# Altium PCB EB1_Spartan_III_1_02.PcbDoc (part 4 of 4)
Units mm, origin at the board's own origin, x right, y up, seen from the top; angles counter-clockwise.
Board outline 165.1 x 115.01 mm, 6 copper layers (Top Layer, MidLayer1, VCC Plane, GND Plane, MidLayer2, Bottom Layer); 356 components, 386 nets, 1788 pads, 779 vias.
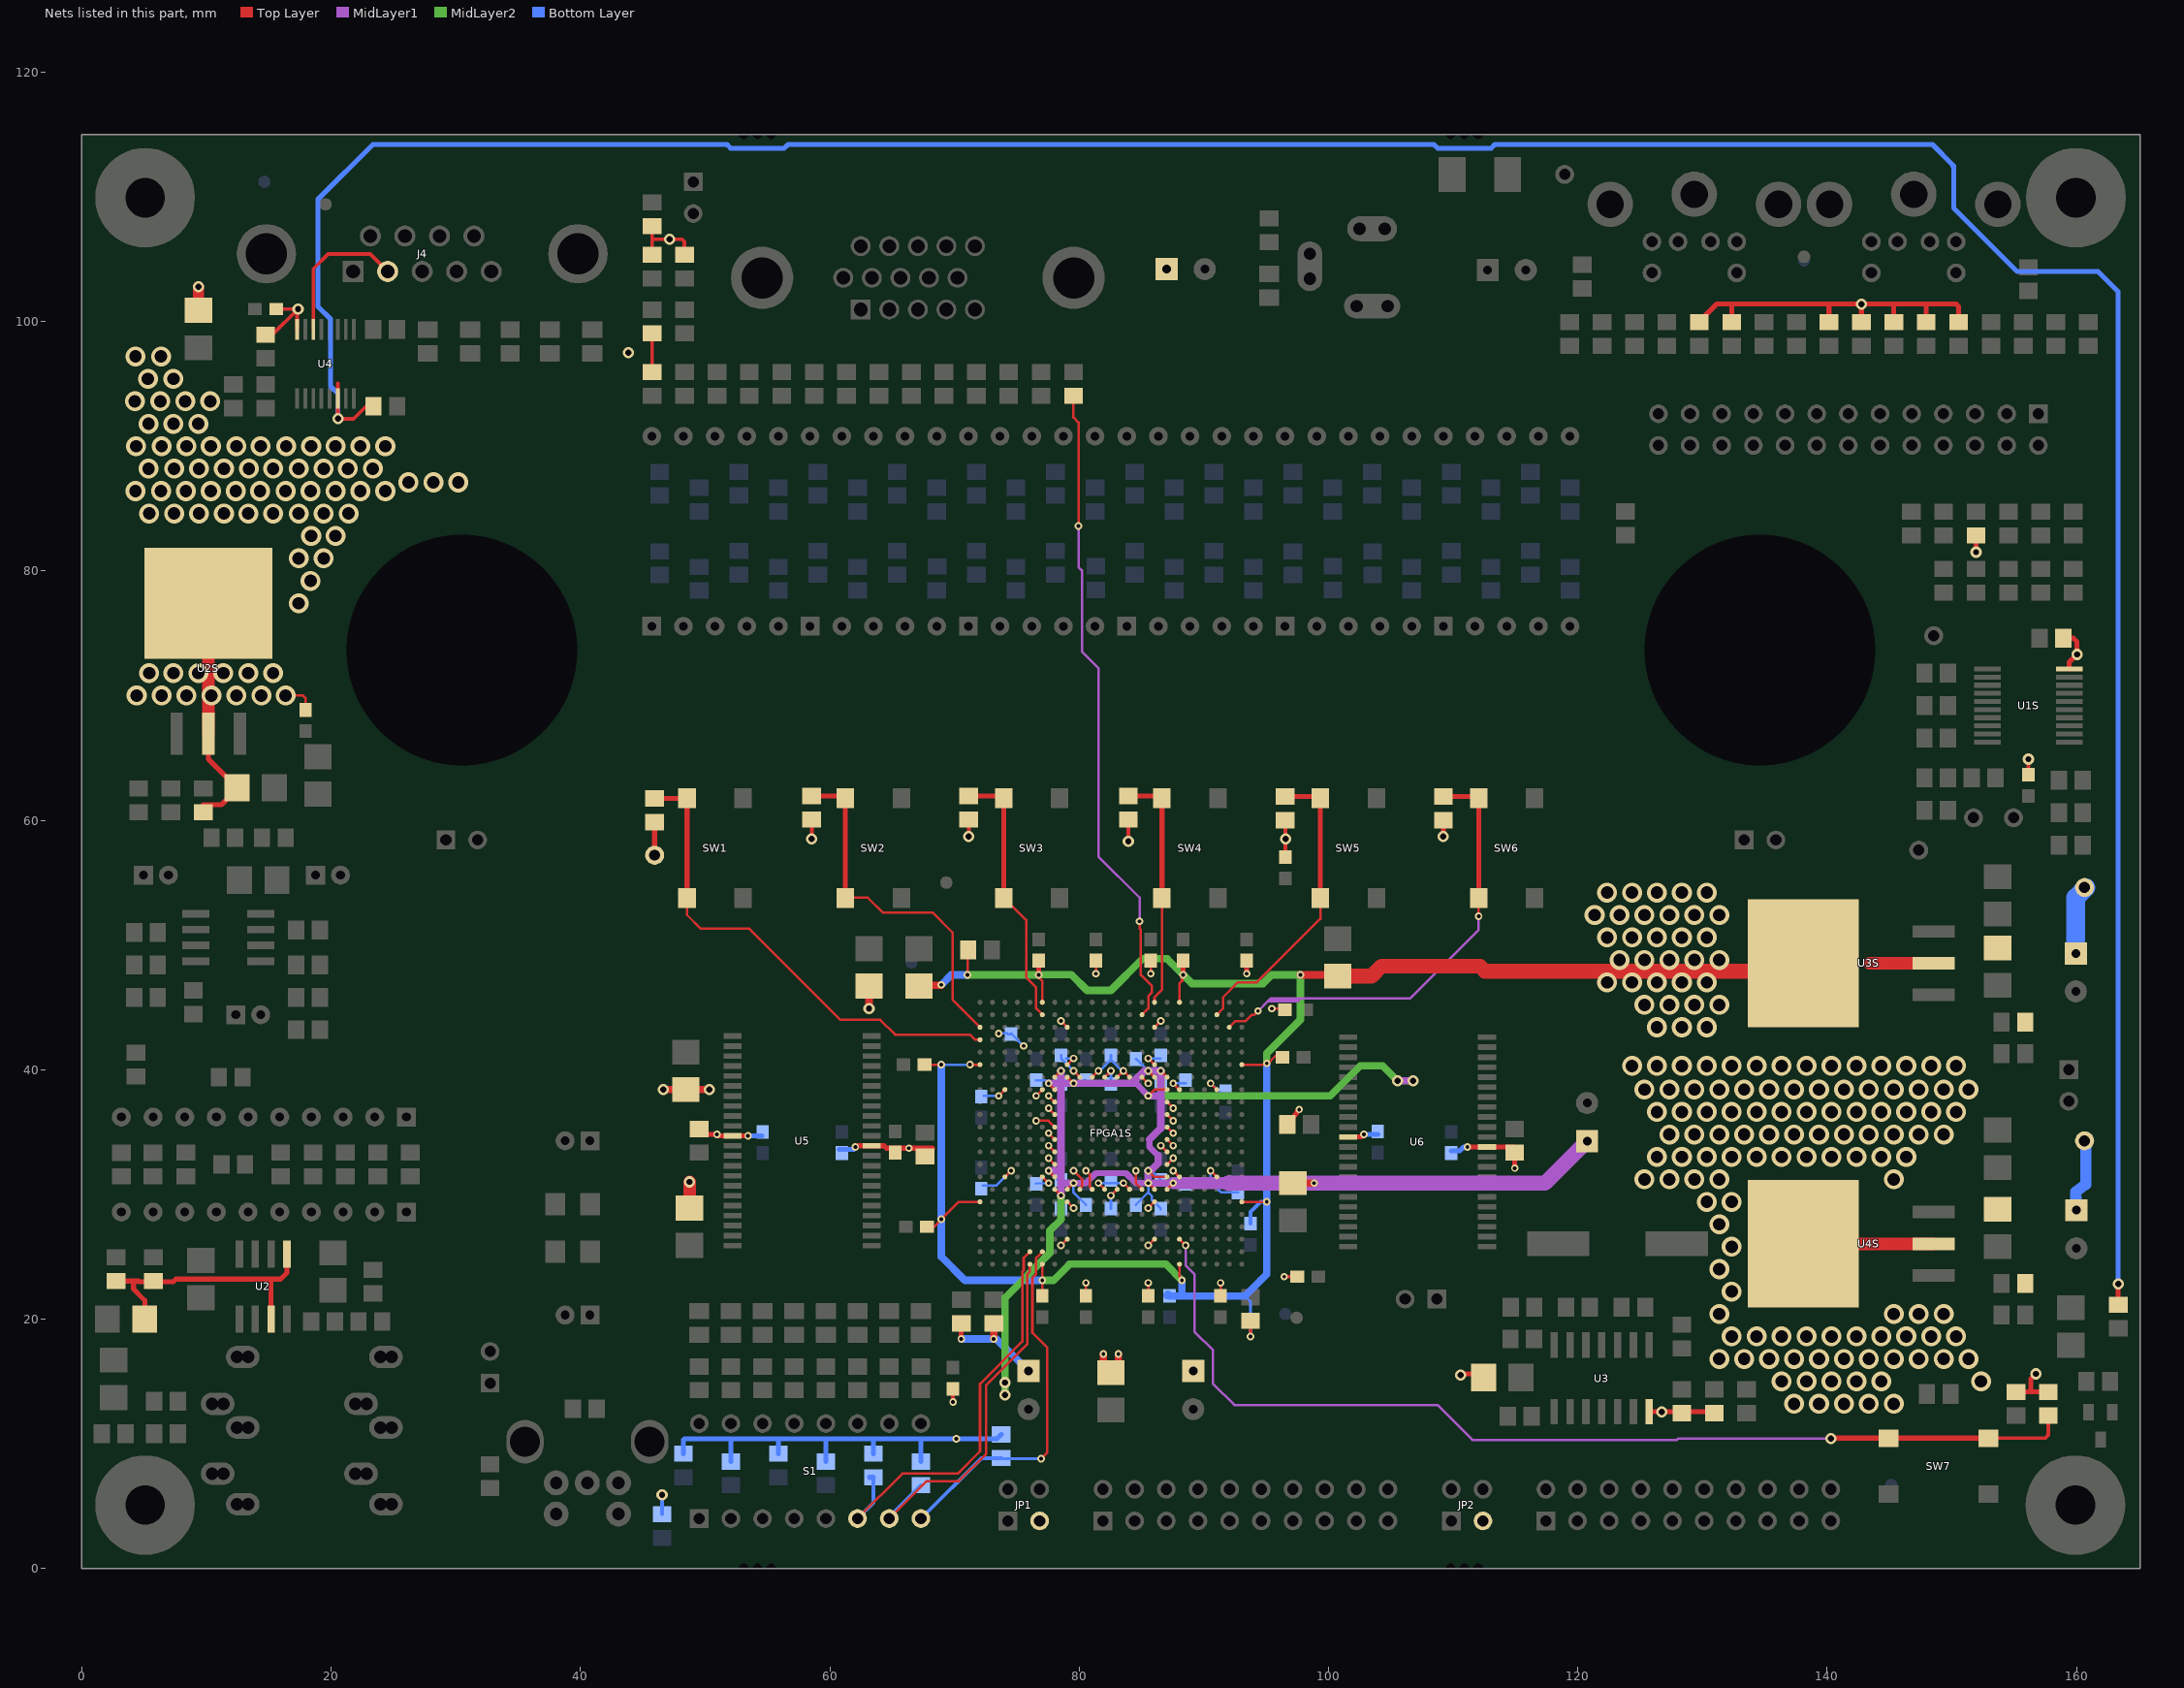
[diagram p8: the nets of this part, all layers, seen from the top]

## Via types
v1: diameter 0.6, hole 0.3, Top Layer to Bottom Layer, tented both sides, 427 vias
v2: diameter 1.6, hole 1, Top Layer to Bottom Layer, 224 vias
v3: diameter 0.9, hole 0.5, Top Layer to Bottom Layer, tented both sides, 126 vias
v4: diameter 1.27, hole 0.711, Top Layer to Bottom Layer, tented both sides, 2 vias

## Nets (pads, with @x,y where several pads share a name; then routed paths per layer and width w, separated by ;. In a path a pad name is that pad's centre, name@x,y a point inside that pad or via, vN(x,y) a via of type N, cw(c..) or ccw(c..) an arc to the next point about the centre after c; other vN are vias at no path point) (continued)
SW_DIP5: FPGA1S.AA5 R16.1 S1.6 | length 33.9
  Top Layer w0.2: S1.6@62.23,4 65.83,7.6 70.25,7.6 72.05,9.4 72.05,14.8 75.45,18.2 75.45,23.8 75.55,23.9 75.55,24.9 FPGA1S.AA5@76.05,25.4
  Bottom Layer w0.3: S1.6@62.23,4 63.5,5.27 R16.1@63.5,7.305
  Bottom Layer w0.4: R16.1@63.185,7.305 R16.1@63.5,7.305
SW_DIP6: FPGA1S.AB5 R17.1 S1.7 | length 30.3
  Top Layer w0.2: S1.7@64.77,4 67.77,7 70.35,7 72.55,9.2 72.55,14.7 75.85,18 75.85,23.6 76.05,23.8 FPGA1S.AB5@76.05,24.4
  Bottom Layer w0.3: S1.7@64.77,4 64.77,4.13 R17.1@67.31,6.67
SW_DIP7: FPGA1S.AA6 R18.1 S1.8 | length 29.2
  Top Layer w0.2: v1(76.95,8.8) 77.45,9.3 77.45,17.7 76.25,18.9 76.25,23.3 76.55,23.6 76.55,24.9 FPGA1S.AA6@77.05,25.4
  Bottom Layer w0.2: R18.1@73.95,8.8 v1(76.95,8.8)
  Bottom Layer w0.3: S1.8@67.31,4 72.16,8.85 R18.1@73.75,8.85
  Bottom Layer w0.4: S1.8@67.09,4.07 S1.8@67.165,4.145
SW_TEST: FPGA1S.Y17 R21.2 SW7.1 SW7.2 | length 83.3
  Top Layer w0.2: FPGA1S.Y17@88.05,26.4 v1(88.55,25.9)
  Top Layer w0.3: SW7.2@153.09,10.45 157.5,10.45 157.75,10.7 R21.2@157.75,12.25
  Top Layer w0.4: v3(140.29,10.4) 140.34,10.45 SW7.1@144.94,10.45 SW7.2@152.95,10.45 SW7.2@153.09,10.45
  MidLayer1 w0.2: v1(88.55,25.9) 88.55,24.3 89.25,23.6 89.25,19 90.75,17.5 90.75,14.8 92.45,13.1 108.75,13.1 111.55,10.3 127.95,10.3 128.05,10.4 v3(140.29,10.4)
SW_USER0: FPGA1S.D1 R9.2 SW1.1 SW1.2 | length 39.6
  Top Layer w0.2: SW1.1@48.55,53.775 48.55,52.4 49.65,51.3 53.55,51.3 60.85,44 64.05,44 65.25,42.8 71.25,42.8 71.65,42.4 FPGA1S.D1@72.05,42.4
  Top Layer w0.4: R9.2@45.95,61.75 48.515,61.75 SW1.2@48.55,61.785 SW1.1@48.55,53.775
SW_USER1: FPGA1S.C1 R10.2 SW2.1 SW2.2 | length 29
  Top Layer w0.2: SW2.1@61.25,53.8 63.05,53.8 64.25,52.6 68.25,52.6 69.85,51 69.85,45.6 FPGA1S.C1@72.05,43.4
  Top Layer w0.4: R10.2@58.55,61.95 61.085,61.95 SW2.2@61.25,61.785 61.25,53.8 SW2.1@61.25,53.775
SW_USER2: FPGA1S.B6 R19.2 SW3.1 SW3.2 | length 21.5
  Top Layer w0.2: SW3.1@73.95,53.775 73.975,53.775 75.75,52 75.75,47.4 76.55,46.6 76.55,44.9 FPGA1S.B6@77.05,44.4
  Top Layer w0.4: R19.2@71.15,61.95 73.9,61.95 SW3.2@73.95,62 ; SW3.1@73.95,53.775 SW3.2@73.95,61.785
SW_USER3: FPGA1S.A15 R20.2 SW4.1 SW4.2 | length 19.3
  Top Layer w0.2: FPGA1S.A15@86.05,45.4 86.05,45.8 86.65,46.4 SW4.1@86.65,53.775
  Top Layer w0.4: R20.2@83.95,61.95 86.5,61.95 SW4.2@86.55,62 ; SW4.1@86.65,53.775 SW4.2@86.65,61.785
SW_USER4: FPGA1S.B20 R22.2 SW5.1 SW5.2 | length 24.6
  Top Layer w0.2: FPGA1S.B20@91.05,44.4 91.55,44.9 91.55,45.8 92.75,47 94.25,47 99.35,52.1 SW5.1@99.35,53.775
  Top Layer w0.4: R22.2@96.52,61.91 99.225,61.91 SW5.2@99.35,61.785 SW5.1@99.35,53.775
SW_USER5: FPGA1S.C21 R23.2 SW6.1 SW6.2 | length 39.4
  Top Layer w0.2: FPGA1S.C21@92.05,43.4 92.55,43.9 93.35,43.9 93.85,44.4 94.05,44.4 v1(94.35,44.7) ; v1(112.05,52.3) SW6.1@112.05,53.775
  Top Layer w0.4: R23.2@109.22,61.91 111.925,61.91 SW6.2@112.05,61.785 SW6.1@112.05,53.775
  MidLayer1 w0.2: v1(94.35,44.7) 95.15,45.5 ; v1(112.05,52.3) 112.05,51.2 106.55,45.7 97.75,45.7 ; 95.15,45.5 97.55,45.5 97.75,45.7 ; 95.15,45.5 95.35,45.7 97.75,45.7
TX: J4.2 U4.14 | length 11.9
  Top Layer w0.3: U4.14@18.575,99.375 18.575,104.225 19.75,105.4 23.15,105.4 J4.2@24.535,104.015
V-232: C23.1 R30S.2 U4.6 | length 259.5
  Top Layer w0.3: 20.525,95.025 U4.6@20.525,93.825 20.525,92.425 v3(20.55,92.2) 21.8,92.2 23.1,93.5 C23.1@23.4,93.8
  Top Layer w0.4: R30S.2@163.35,21.15 v3(163.35,22.8)
  Bottom Layer w0.4: v3(20.55,92.2) 20.55,94.2 19.95,94.8 19.95,100.2 18.95,101.2 18.95,109.8 23.35,114.2 51.75,114.2 52.05,113.9 56.35,113.9 56.65,114.2 108.45,114.2 108.75,113.9 113.05,113.9 113.35,114.2 148.45,114.2 150.15,112.5 150.15,112.4 ; 150.1,112.45 150.15,112.4 ; v3(163.35,22.8) 163.35,102.4 161.75,104 155.25,104 150.15,109.1 150.15,112.4
VAREF: C4.1 R7.2 R8.1 U2.3 U2.5 | length 22.4
  Top Layer w0.4: R8.1@2.75,23.05 4.15,23.05 ; 4.55,23 5.75,23 7.35,23 7.55,23.2 15.15,23.2 ; 4.55,23.05 4.15,23.05 ; C4.1@5.05,20 5.05,21.5 4.15,22.4 4.15,23.05 ; U2.3@15.185,20 15.185,23.165 15.15,23.2 ; U2.5@16.455,25.2 16.455,23.705 16.195,23.445 15.95,23.2 15.15,23.2
  Top Layer w0.6: R7.2@5.75,23.05 5.8,23.05 R7.2@5.95,23.2
VCC: C1S.1 C2S.1 C3S.1 C4S.1 C5S.1 C6S.1 C7S.1 C8S.1 C13S.1 C14S.1 C15S.1 C16S.1 C17S.1 C18.1 C18S.1 C19.1 C19S.1 C20S.1 C21.1 C21S.1 C22S.1 C23S.1 C24.1 C24S.1 C25.2 C25S.1 C26.2 C26S.1 C27.2 C27S.1 C28.2 C28S.1 C29.2 C29S.1 C30S.1 C31S.1 C32S.1 C33S.1 C34S.1 C51S.1 C54S.1 C55S.1 C56S.1 C57S.1 C68S.1 C69S.1 C74S.1 C80S.1 FPGA1S.C8 FPGA1S.C15 FPGA1S.F8 FPGA1S.F15 FPGA1S.G9 FPGA1S.G10 FPGA1S.G11 FPGA1S.G12 FPGA1S.G13 FPGA1S.G14 FPGA1S.H3 FPGA1S.H6 FPGA1S.H17 FPGA1S.H20 FPGA1S.J7 FPGA1S.J16 FPGA1S.K7 FPGA1S.K16 FPGA1S.L7 FPGA1S.L16 FPGA1S.M7 FPGA1S.M16 FPGA1S.N7 FPGA1S.N16 FPGA1S.P7 FPGA1S.P16 FPGA1S.R3 FPGA1S.R6 FPGA1S.R17 FPGA1S.R20 FPGA1S.T9 FPGA1S.T10 FPGA1S.T11 FPGA1S.T12 FPGA1S.T13 FPGA1S.T14 FPGA1S.U8 FPGA1S.U15 FPGA1S.Y8 FPGA1S.Y15 JP1.3 JP2.3 R9.1 R10.1 R11.2 R12.2 R13.2 R13S.1 R14.2 R14S.1 R15.2 R15S.1 R16.2 R16S.1 R17.2 R17S.1 R18.2 R18S.1 R19.1 R19S.1 R20.1 R20S.1 R21.1 R22.1 R23.1 R32S.2 R73.2 R82.1 R96.2 R97.2 R98.2 R99.2 TP7S.1 U1S.20 U2S.2 U2S.4 U3.14 U4.16 U5.11 U5.33 U6.11 U6.33 | length 231.3
  Top Layer w0.2: v2(16.35,70) 17.75,70 17.95,69.8 C3S.1@17.95,68.85 ; v1(73.55,37.9) FPGA1S.H3@74.05,38.4 ; FPGA1S.R3@74.05,31.4 v1(74.55,31.9) ; v1(76.55,35.9) 77.55,35.9 FPGA1S.L7@78.05,35.4 ; v1(76.55,37.9) FPGA1S.H6@77.05,38.4 ; FPGA1S.R6@77.05,31.4 v1(77.55,30.9) ; v1(77.55,32.9) FPGA1S.P7@78.05,32.4 ; v1(77.55,33.9) FPGA1S.N7@78.05,33.4 ; v1(77.55,34.9) FPGA1S.M7@78.05,34.4 ; v1(77.55,36.9) FPGA1S.K7@78.05,36.4 ; v1(77.55,37.9) FPGA1S.J7@78.05,37.4 ; v1(78.55,25.9) FPGA1S.Y8@79.05,26.4 ; v1(78.55,43.9) FPGA1S.C8@79.05,43.4 ; FPGA1S.U8@79.05,29.4 v1(79.55,28.9) ; FPGA1S.F8@79.05,40.4 v1(79.55,40.9) ; v1(79.55,31.9) 80.25,31.2 80.25,30.7 FPGA1S.T9@80.05,30.4 ; v1(79.55,39.9) FPGA1S.G9@80.05,39.4 ; C7S.1@80.55,21.85 v1(80.55,22.9) ; v1(80.55,31.9) 80.85,31.6 80.85,30.6 FPGA1S.T10@81.05,30.4 ; FPGA1S.G10@81.05,39.4 v1(81.55,39.9) ; v1(81.35,47.7) C16S.1@81.35,48.7 ; v1(81.55,30.9) FPGA1S.T11@82.05,30.4 ; FPGA1S.G11@82.05,39.4 v1(82.55,39.9) ; v1(82.55,29.9) FPGA1S.T12@83.05,30.4 ; FPGA1S.G12@83.05,39.4 v1(83.55,39.9) 83.95,39.5 FPGA1S.G13@84.05,39.4 ; v1(83.55,30.9) FPGA1S.T13@84.05,30.4 ; v1(84.55,31.9) 84.55,30.9 FPGA1S.T14@85.05,30.4 ; FPGA1S.G14@85.05,39.4 v1(85.55,38.9) ; C29S.1@85.55,21.85 v1(85.55,22.9) v1@85.55,23 ; v1(85.55,25.9) FPGA1S.Y15@86.05,26.4 ; v1(85.55,28.9) FPGA1S.U15@86.05,29.4 ; v1(85.55,40.9) FPGA1S.F15@86.05,40.4 ; v1(85.75,47.7) C24S.1@85.75,48.75 ; FPGA1S.C15@86.05,43.4 v1(86.55,43.9) ; v1(86.55,33.9) FPGA1S.N16@87.05,33.4 ; FPGA1S.P16@87.05,32.4 v1(87.55,32.9) ; FPGA1S.M16@87.05,34.4 v1(87.55,33.9) ; FPGA1S.L16@87.05,35.4 v1(87.55,34.9) ; FPGA1S.K16@87.05,36.4 v1(87.55,35.9) ; FPGA1S.J16@87.05,37.4 v1(87.55,36.9) ; v1(87.55,31.9) FPGA1S.R17@88.05,31.4 ; v1(87.55,38.9) FPGA1S.H17@88.05,38.4 ; v1(90.55,31.9) FPGA1S.R20@91.05,31.4 ; v1(90.55,38.9) FPGA1S.H20@91.05,38.4 ; C2S.1@91.35,21.85 91.35,22.8 v1(91.35,22.9) ; v1(95.45,44.9) 96.5,44.9 96.55,44.9 96.532,44.795 C1S.1@96.5,44.6
  Top Layer w0.3: C21.1@14.75,98.95 15.3,98.95 v3@17.275,100.925 ; C26S.1@15.6,101 v3(17.35,101) v3@17.275,100.925 ; U4.16@17.275,99.375 v3@17.275,100.925 ; C24.1@45.75,95.95 R96.2@45.75,99.05 ; R97.2@45.75,105.35 45.75,106.6 ; R99.2@45.75,107.65 45.75,106.6 ; R98.2@48.35,105.35 48.35,106.4 48.15,106.6 v3(47.15,106.6) 45.75,106.6 ; v3(58.55,58.5) R10.1@58.55,60.05 R10.1@58.55,60.1 ; v1(69.885,13.345) C13S.1@69.885,14.395 C13S.1@69.885,14.445 ; v3(71.15,58.7) R19.1@71.15,60.05 ; v3(83.95,58.3) R20.1@83.95,60 ; v1(96.45,23.4) C8S.1@97.5,23.4 C8S.1@97.55,23.4 ; R22.1@96.52,60.01 96.55,59.98 v3(96.55,58.5) C25S.1@96.55,57.05 C25S.1@96.55,57 ; C21S.1@156.15,63.65 v3(156.15,64.9)
  Top Layer w0.4: R32S.2@9.75,61.25 11.2,61.25 12.45,62.5 C74S.1@12.45,62.6 10.15,64.9 U2S.2@10.15,66.95 ; TP7S.1@45.95,57.2 R9.1@45.95,59.85 ; C26.2@49.55,34.8 v1(50.95,34.8) 51.06,34.69 U5.11@52.21,34.69 v1(53.44,34.69) ; v1(62.05,33.8) 62.25,33.9 63.36,33.9 U5.33@63.45,33.9 ; U5.33@63.36,33.89 64.36,33.89 64.55,33.7 65.25,33.7 v1(66.35,33.7) 67.65,33.7 68.25,33.7 ; v1(93.45,47.7) C4S.1@93.45,48.75 ; C27.2@97.05,36 v1(97.65,36.8) ; U6.11@101.575,34.6 102.65,34.6 v1(102.85,34.8) ; v3(109.2,58.7) 109.22,58.72 R23.1@109.22,60.01 ; v3(110.6,15.5) 110.7,15.6 C56S.1@112.45,15.6 ; v1(111.15,33.8) U6.33@112.725,33.8 ; U6.33@112.75,33.8 U6.33@112.725,33.8 ; v1(114.95,32.1) C25.2@114.95,33.3 ; C25.2@114.95,33.8 114.935,33.8 U6.33@112.725,33.8 ; U3.14@125.73,12.565 v3(126.75,12.565) 128.35,12.565 130.435,12.565 R82.1@130.55,12.45 ; R19S.1@129.75,99.95 129.75,100 131.15,101.4 132.35,101.4 ; R18S.1@132.35,100.1 132.35,101.4 ; R17S.1@140.15,99.95 140.15,101.4 ; R16S.1@142.75,99.95 v3(142.75,101.4) ; R15S.1@145.35,99.95 145.35,101.4 ; R20S.1@147.95,99.95 147.95,101.4 ; R14S.1@150.55,99.95 150.55,101.2 150.35,101.4 147.95,101.4 ; v3(151.95,81.5) R13S.1@151.95,82.85 ; R73.2@155.15,14.15 156.35,14.15 ; v3(156.75,15.6) 156.35,15.2 156.35,14.15 ; R21.1@157.75,14.15 156.35,14.15 ; C68S.1@158.85,74.6 C68S.1@158.95,74.6 159.75,74.6 160.05,74.3 v3(160.05,73.3) 159.425,72.675 U1S.20@159.425,72.125 ; 132.35,101.4 140.15,101.4 ; 140.15,101.4 v3(142.75,101.4) ; v3(142.75,101.4) 145.35,101.4 ; 145.35,101.4 147.95,101.4
  Top Layer w0.6: v3(46.65,38.4) C55S.1@48.45,38.4 v3(50.35,38.4) ; v3(63.15,44.9) C54S.1@63.15,46.7 ; C57S.1@81.95,15.7 v1(81.95,17.2) ; C57S.1@83.15,16.2 v1(83.15,17.2)
  Top Layer w0.9: C18.1@9.35,100.8 C18.1@9.35,100.9 v3(9.35,102.8)
  Top Layer w1: U2S.4@10.05,74.6 10.15,74.5 10.15,71.8 10.15,70 U2S.2@10.15,66.95 ; C19.1@48.75,28.9 v3(48.75,31)
  Bottom Layer w0.2: C15S.1@72.25,30.7 73.35,30.7 v1(74.55,31.9) ; C27S.1@72.35,37.9 v1(73.55,37.9) ; v1(73.55,42.9) 74.25,42.9 74.3,42.85 C34S.1@74.55,42.85 ; C34S.1@74.55,42.9 74.575,42.875 v1(75.55,41.9) ; C5S.1@76.55,30.85 v1(77.55,30.9) ; C32S.1@78.55,41.15 78.55,40.9 v1(79.55,39.9) ; C32S.1@78.95,40.9 v1(79.55,40.9) ; v1(81.55,30.9) 82.55,30.9 v1(83.55,30.9) ; v1(81.55,39.9) 81.65,39.9 C28S.1@82.55,40.8 ; C80S.1@82.55,28.85 v1(82.55,29.9) ; C23S.1@82.55,38.85 v1(82.55,39.9) ; C28S.1@82.55,41.15 C28S.1@82.55,40.8 ; v1@83.55,40 v1(83.55,39.9) 83.45,39.9 C28S.1@82.55,40.8 ; v1(85.55,40.9) C19S.1@86.55,40.9 ; v1(87.55,38.9) C31S.1@88.55,38.9 ; v1(90.55,31.9) 90.55,31 91.4,30.15 C14S.1@92.75,30.15 ; v1(90.55,38.9) 91.531,38.009 C33S.1@91.65,37.9
  Bottom Layer w0.3: R11.2@46.55,4.35 v3(46.55,5.9)
  Bottom Layer w0.4: R12.2@48.26,9.205 48.26,10.31 48.35,10.4 52.15,10.4 ; R13.2@52.07,8.57 52.07,10.32 52.15,10.4 ; v1(53.44,34.69) 53.45,34.7 C18S.1@54.55,34.7 ; R14.2@55.88,9.205 55.88,10.27 55.75,10.4 ; R15.2@59.69,8.57 59.69,10.34 59.75,10.4 ; C17S.1@60.75,33.6 60.96,33.6 61.95,33.6 v1(62.05,33.8) ; R16.2@63.5,9.205 63.5,10.35 63.55,10.4 ; R17.2@67.31,8.57 67.31,10.36 67.27,10.4 ; R18.2@73.75,10.75 73.4,10.4 v1(70.15,10.4) 67.27,10.4 ; v1(102.85,34.8) C20S.1@103.95,34.8 ; C6S.1@109.85,33.5 109.855,33.5 110.55,33.5 110.85,33.8 v1(111.15,33.8) ; v3@151.85,81.4 v3(151.95,81.5) ; 52.15,10.4 55.75,10.4 ; 55.75,10.4 59.75,10.4 ; 59.75,10.4 63.55,10.4 ; 63.55,10.4 67.27,10.4
  other v2: 4.4,70 6.4,70 8.4,70 10.4,70 12.4,70 14.4,70 5.4,71.8 7.35,71.8 9.35,71.8 11.35,71.8 13.35,71.8 15.35,71.8 17.4,77.4 18.35,79.2 17.4,81 19.4,81 18.4,82.8 20.35,82.8 5.4,84.6 7.4,84.6 9.4,84.6 11.4,84.6 13.35,84.6 15.35,84.6 17.4,84.6 19.4,84.6 21.4,84.6 4.3,86.4 6.35,86.4 8.35,86.4 10.35,86.4 12.35,86.4 14.3,86.4 16.35,86.4 18.35,86.4 20.35,86.4 22.35,86.4 24.35,86.4 26.2,87.1 28.2,87.1 30.2,87.1 5.35,88.2 7.4,88.2 9.4,88.2 11.4,88.2 13.4,88.2 15.35,88.2 17.4,88.2 19.4,88.2 21.35,88.2 23.35,88.2 4.35,90 6.4,90 8.4,90 10.35,90 12.4,90 14.35,90 16.4,90 18.4,90 20.35,90 22.35,90 24.35,90 5.35,91.8 7.35,91.8 9.35,91.8 4.25,93.6 6.3,93.6 8.3,93.6 10.3,93.6 5.3,95.4 7.35,95.4 4.3,97.2 6.35,97.2
  other v3: 43.85,97.5
VCCAUX: C9S.1 C10S.1 C35S.1 C36S.1 C37S.1 C38S.1 C39S.1 C40S.1 C52S.1 C58S.1 C59S.1 C71S.1 C76S.1 FPGA1S.A6 FPGA1S.A17 FPGA1S.AB6 FPGA1S.AB17 FPGA1S.F1 FPGA1S.F22 FPGA1S.U1 FPGA1S.U22 R1S.1 R2S.1 R3S.1 R4S.1 R33S.2 TP5S.1 U3S.2 U3S.4 | length 202.6
  Top Layer w0.2: C35S.1@67.6,27.4 C35S.1@67.8,27.4 68.35,27.4 v1(68.95,28) 70.35,29.4 FPGA1S.U1@72.05,29.4 ; C10S.1@67.6,40.4 v1(68.95,40.4) ; v1(71.05,47.6) 71.05,49.1 71.1,49.15 R2S.1@71.1,49.6 ; v1(76.75,47.6) 76.835,47.315 77.05,47.1 FPGA1S.A6@77.05,45.4 ; C36S.1@76.835,21.805 76.835,21.85 76.841,21.886 76.844,21.903 76.886,21.963 76.919,22.01 77.05,22.2 v1(77.05,23.1) 77.05,23.3 FPGA1S.AB6@77.05,24.4 ; FPGA1S.AB17@88.05,24.4 88.05,23.4 v1(88.25,23.1) ; FPGA1S.A17@88.05,45.4 88.05,46.9 88.265,47.115 v1@88.265,47.6 ; FPGA1S.U22@93.05,29.4 v1(95.05,29.4) ; FPGA1S.F22@93.05,40.4 95.05,40.4 95.1,40.45 95.75,41.1 96.3,41.1 C38S.1@96.4,41.1 ; v1(93.75,18.6) R1S.1@93.75,19.85 ; v1(71.25,40.4) FPGA1S.F1@72.05,40.4 v1(71.25,40.4)
  Top Layer w0.4: v1(70.55,18.4) R3S.1@70.55,19.65 ; v1(76.75,47.6) C40S.1@76.75,48.75 ; v1(88.35,47.6) C39S.1@88.35,48.75
  Top Layer w0.6: C58S.1@67.15,46.76 v1@68.91,46.76 ; C58S.1@67.15,46.8 C58S.1@67.16,46.8 ; v1(73.15,18.4) R4S.1@73.15,19.65 ; v1(97.75,47.6) 100.65,47.6 C59S.1@100.75,47.5
  Top Layer w1: 143.39,48.54 U3S.2@148.55,48.54
  Top Layer w1.2: C59S.1@100.75,47.5 103.45,47.5 104.25,48.3 112.15,48.3 112.55,47.9 122.35,47.9 123.35,47.9 124.35,47.9 125.35,47.9 126.35,47.9 127.35,47.9 128.35,47.9 129.35,47.9 130.35,47.9 131.35,47.9 137.3,47.9 138.02,48.62 U3S.4@138.1,48.7
  MidLayer2 w0.6: v1(71.05,47.6) v1(76.75,47.6) ; v1@76.835,47.625 79.375,47.625 80.645,46.355 82.55,46.355 85.09,48.895 87.055,48.895 v1(88.35,47.6) 89.05,46.9 94.75,46.9 95.45,47.6 v1(97.75,47.6) 97.75,44 95.05,41.3 v1(95.05,40.5) ; v1(77.05,23.1) 77.95,23.1 79.25,24.4 86.95,24.4 v1(88.25,23.1)
  Bottom Layer w0.2: v1(68.95,40.4) v1(71.25,40.4) ; 93.3,21.85 93.75,21.4 v1(93.75,18.6)
  Bottom Layer w0.3: C9S.1@93.75,27.65 93.75,28.6 94.55,29.4 v1(95.05,29.4)
  Bottom Layer w0.6: v1(68.95,40.4) v1(68.95,28) 68.95,25 70.85,23.1 v1(77.05,23.1) ; v1(68.95,46.8) 69.75,47.6 v1(71.05,47.6) ; v1(70.55,18.4) v1(73.15,18.4) 73.35,18.4 C52S.1@75.95,15.824 ; C37S.1@87.125,21.975 87.05,21.9 C37S.1@87.25,21.9 ; C37S.1@87.25,21.85 88.25,21.85 ; v1(88.25,23.1) 88.25,21.85 ; v1(95.05,40.5) v1(95.05,29.4) 95.05,23.6 94.55,23.1 93.3,21.85 88.25,21.85
  Bottom Layer w1.5: C71S.1@159.95,49.324 159.95,53.8 160.707,54.557 TP5S.1@160.75,54.6
  other v2: 126.35,43.4 128.35,43.4 130.35,43.4 125.35,45.2 127.35,45.2 129.35,45.2 131.35,45.2 122.35,47 124.35,47 126.35,47 128.35,47 130.35,47 123.35,48.8 125.35,48.8 127.35,48.8 129.35,48.8 131.35,48.8 122.35,50.6 124.35,50.6 126.35,50.6 128.35,50.6 130.35,50.6 121.35,52.4 123.35,52.4 125.35,52.4 127.35,52.4 129.35,52.4 131.35,52.4 122.35,54.2 124.35,54.2 126.35,54.2 128.35,54.2 130.35,54.2
VCCINT: C11S.1 C12S.1 C41S.1 C42S.1 C43S.1 C44S.1 C45S.1 C46S.1 C47S.1 C48S.1 C49S.1 C50S.1 C53S.1 C60S.1 C72S.1 C78S.1 FPGA1S.G7 FPGA1S.G8 FPGA1S.G15 FPGA1S.G16 FPGA1S.H7 FPGA1S.H16 FPGA1S.R7 FPGA1S.R16 FPGA1S.T7 FPGA1S.T8 FPGA1S.T15 FPGA1S.T16 R37S.2 TP8S.1 U4S.2 U4S.4 | length 162.1
  Top Layer w0.2: v1(77.55,31.9) FPGA1S.R7@78.05,31.4 ; v1(77.55,38.9) FPGA1S.H7@78.05,38.4 ; FPGA1S.T7@78.05,30.4 v1(78.55,29.9) ; FPGA1S.G7@78.05,39.4 v1(78.55,39.9) ; FPGA1S.T8@79.05,30.4 v1(79.55,30.9) ; FPGA1S.G8@79.05,39.4 v1(79.55,38.9) ; v1(85.55,30.9) FPGA1S.T15@86.05,30.4 ; v1(85.55,31.9) 86.05,31.4 FPGA1S.R16@87.05,31.4 ; v1(85.55,37.9) 86.05,38.4 FPGA1S.H16@87.05,38.4 ; v1(85.55,39.9) FPGA1S.G15@86.05,39.4 ; v1(86.55,39.9) FPGA1S.G16@87.05,39.4 ; FPGA1S.T16@87.05,30.4 v1(87.55,30.9)
  Top Layer w0.6: C60S.1@97.15,30.9 v1(98.85,30.9)
  Top Layer w1: U4S.4@141.65,25.9 141.785,26.035 U4S.2@148.55,26.035
  MidLayer1 w0.5: v1(79.55,30.9) 80.55,30.9 81.35,31.7 83.75,31.7 84.55,30.9 v1(85.55,30.9) ; 84.55,38.9 v1(85.55,37.9) ; 85.65,34.4 85.65,33.8 86.35,33.1
  MidLayer1 w0.6: v1(77.55,31.9) 78.55,31.9 ; v1(77.55,38.9) 78.55,38.9 ; v1(78.55,29.9) 78.55,30.9 ; v1(78.55,39.9) 78.55,38.9 ; v1(79.55,30.9) 78.55,30.9 ; 84.55,38.9 84.45,38.9 ; v1(85.55,31.9) v1@85.55,31.7 ; v1(85.55,37.9) 86.45,37.9 86.55,38 ; 85.65,34.4 86.55,35.3 86.55,38 ; 86.35,33.1 86.35,32.5 85.65,31.8 v1@85.55,31.7 ; v1(87.55,30.9) v1(85.55,30.9) v1@85.55,31.7 ; v3(105.55,39.1) v3(106.8,39.1) ; 78.55,30.9 78.55,31.9 ; 78.55,31.9 78.55,38.9 ; 78.55,38.9 v1(79.55,38.9) 84.45,38.9 ; 84.45,38.9 84.45,39.1 85.25,39.9 v1(85.55,39.9) v1(86.55,39.9) 86.55,38
  MidLayer1 w1: v1(87.55,30.9) 91.95,30.9
  MidLayer1 w1.2: 91.95,30.9 v1(98.85,30.9) 117.374,30.9 C53S.1@120.75,34.276
  MidLayer2 w0.6: v3(74.05,13.9) v3(74.05,14.9) 74.05,21.7 77.65,25.3 77.65,27.1 78.55,28 v1(78.55,29.9) ; v1(86.55,39.9) 86.55,38.4 87.05,37.9 100.15,37.9 102.55,40.3 104.35,40.3 v3(105.55,39.1) v3(106.8,39.1)
  Bottom Layer w0.2: C45S.1@76.55,39.15 77.3,39.15 v1(77.55,38.9) ; v1(77.55,31.9) 78.3,31.15 C11S.1@78.55,31.15 ; C50S.1@78.55,28.85 78.55,28.9 v1(78.55,29.9) ; C49S.1@78.55,38.85 v1(78.55,39.9) ; v1(79.55,30.9) 79.55,30.15 C47S.1@80.55,29.15 ; v1(79.55,38.9) 80.15,38.9 80.4,39.15 C12S.1@80.55,39.15 ; C43S.1@84.55,29.15 85.525,30.125 85.55,30.15 ; C44S.1@84.55,40.85 84.6,40.85 v1(85.55,39.9) ; 85.55,30.1 85.6,30.1 85.85,29.85 85.85,29.55 C46S.1@86.55,28.85 C46S.1@86.55,28.8 ; v1(85.55,30.9) 85.55,30.15 ; v1(85.55,31.9) 85.8,31.9 C42S.1@86.55,31.15 ; 85.575,30.125 85.55,30.15 ; C41S.1@86.55,38.85 v1(86.55,39.9) ; v1(87.55,30.9) 88.5,30.9 C48S.1@88.55,30.85
  Bottom Layer w0.9: C72S.1@160,28.724 159.95,30.2 160.75,30.8 160.75,34.29 160.75,34.4 TP8S.1@160.655,34.29 160.655,34.395 TP8S.1@160.65,34.4
  other v2: 137.35,13.2 139.35,13.2 141.35,13.2 143.35,13.2 145.35,13.2 136.35,15 138.35,15 140.35,15 142.35,15 144.35,15 152.35,15 131.35,16.8 133.35,16.8 135.35,16.8 137.35,16.8 139.35,16.8 141.35,16.8 143.35,16.8 145.35,16.8 147.35,16.8 149.35,16.8 149.35,16.8 151.35,16.8 132.35,18.6 134.35,18.6 136.35,18.6 138.35,18.6 140.35,18.6 142.35,18.6 144.35,18.6 146.35,18.6 148.35,18.6 150.35,18.6 131.35,20.4 145.35,20.4 147.35,20.4 149.35,20.4 132.35,22.2 131.35,24 132.35,25.8 131.35,27.6 130.35,29.4 132.35,29.4 125.35,31.2 127.35,31.2 129.35,31.2 131.35,31.2 145.35,31.2 126.35,33 128.35,33 130.35,33 132.35,33 134.35,33 136.35,33 138.35,33 140.35,33 142.35,33 144.35,33 146.35,33 127.35,34.8 129.35,34.8 131.35,34.8 133.35,34.8 135.35,34.8 137.35,34.8 139.35,34.8 141.35,34.8 143.35,34.8 145.35,34.8 147.35,34.8 149.35,34.8 126.35,36.6 128.35,36.6 130.35,36.6 132.35,36.6 134.35,36.6 136.35,36.6 138.35,36.6 140.35,36.6 142.35,36.6 144.35,36.6 146.35,36.6 148.35,36.6 150.35,36.6 125.35,38.4 127.35,38.4 129.35,38.4 131.35,38.4 133.35,38.4 135.35,38.4 137.35,38.4 139.35,38.4 141.35,38.4 143.35,38.4 145.35,38.4 147.35,38.4 149.35,38.4 151.35,38.4 124.35,40.3 126.35,40.3 128.35,40.3 130.35,40.3 132.35,40.3 134.35,40.3 136.35,40.3 138.35,40.3 140.35,40.3 142.35,40.3 144.35,40.3 146.35,40.3 148.35,40.3 150.35,40.3
VSYNC: FPGA1S.B14 R95.1 | length 52.6
  Top Layer w0.2: R95.1@79.55,94.05 79.55,92.3 79.95,91.9 v1(79.95,83.6) ; v1(84.85,51.9) 84.85,51.3 84.95,51.2 84.95,47.6 85.062,47.488 85.85,46.7 85.85,46.2 85.55,45.9 85.55,44.9 FPGA1S.B14@85.05,44.4
  MidLayer1 w0.2: v1(79.95,83.6) 79.95,80.3 80.225,80.025 80.225,73.525 81.55,72.2 81.55,57.1 84.85,53.8 v1(84.85,51.9)
pads on no net: D2S.3 FPGA1S.A3 FPGA1S.A7 FPGA1S.A11 FPGA1S.A16 FPGA1S.AA3 FPGA1S.AA7 FPGA1S.AA9 FPGA1S.AA11 FPGA1S.AA14 FPGA1S.AA16 FPGA1S.AA19 FPGA1S.AB7 FPGA1S.AB9 FPGA1S.AB12 FPGA1S.AB14 FPGA1S.AB16 FPGA1S.AB19 FPGA1S.B4 FPGA1S.B7 FPGA1S.B11 FPGA1S.B12 FPGA1S.B16 FPGA1S.C2 FPGA1S.C3 FPGA1S.C4 FPGA1S.C12 FPGA1S.C16 FPGA1S.D2 FPGA1S.D3 FPGA1S.D4 FPGA1S.D5 FPGA1S.D8 FPGA1S.D12 FPGA1S.D16 FPGA1S.E2 FPGA1S.E3 FPGA1S.E4 FPGA1S.E5 FPGA1S.E8 FPGA1S.E10 FPGA1S.E12 FPGA1S.F4 FPGA1S.F5 FPGA1S.F6 FPGA1S.F9 FPGA1S.F10 FPGA1S.F11 FPGA1S.F12 FPGA1S.F13 FPGA1S.F14 FPGA1S.F16 FPGA1S.G3 FPGA1S.G4 FPGA1S.G5 FPGA1S.G20 FPGA1S.H1 FPGA1S.H2 FPGA1S.H4 FPGA1S.H18 FPGA1S.H19 FPGA1S.H21 FPGA1S.H22 FPGA1S.J1 FPGA1S.J2 FPGA1S.J4 FPGA1S.J5 FPGA1S.J6 FPGA1S.J17 FPGA1S.J18 FPGA1S.J19 FPGA1S.J21 FPGA1S.J22 FPGA1S.K5 FPGA1S.K6 FPGA1S.K17 FPGA1S.K18 FPGA1S.N5 FPGA1S.N6 FPGA1S.N17 FPGA1S.N18 FPGA1S.N19 FPGA1S.N20 FPGA1S.P1 FPGA1S.P2 FPGA1S.P4 FPGA1S.P5 FPGA1S.P6 FPGA1S.P17 FPGA1S.P18 FPGA1S.P19 FPGA1S.P21 FPGA1S.P22 FPGA1S.R1 FPGA1S.R2 FPGA1S.R4 FPGA1S.R5 FPGA1S.R19 FPGA1S.R21 FPGA1S.R22 FPGA1S.T3 FPGA1S.T19 FPGA1S.T20 FPGA1S.U9 FPGA1S.U12 FPGA1S.U13 FPGA1S.U14 FPGA1S.U17 FPGA1S.V11 FPGA1S.V12 FPGA1S.V15 FPGA1S.W7 FPGA1S.W8 FPGA1S.W11 FPGA1S.W12 FPGA1S.W15 FPGA1S.W18 FPGA1S.Y4 FPGA1S.Y7 FPGA1S.Y11 FPGA1S.Y12 J1S.1 J1S.6 J1S.14 J1S.16 J1S.26 J2.2 J2.8 J3.2 J3.8 J4.9 J5.4 J5.9 J5.11 J5.12 J5.15 U3.10 U3.12

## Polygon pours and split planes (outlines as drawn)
GND on Top Layer "Top Layer-GND" (solid, remove dead copper, pour order 1003): 23.63,59.88 23.664,59.8 23.664,41.4 23.63,41.32 23.55,41.286 0.55,41.286 0.47,41.32 0.436,41.4 0.436,59.8 0.47,59.88 0.55,59.914 23.55,59.914
VCCAUX on Top Layer "Top Layer-VCCAUX" (solid, remove dead copper, pour order 1002): 166.688,60.18 166.722,60.1 166.722,59.63 166.864,40.001 166.863,40 166.864,40 166.847,39.96 166.831,39.92 166.83,39.92 166.791,39.903 166.751,39.886 166.75,39.887 166.75,39.886 151.968,39.886 151.932,39.901 151.895,39.912 148.658,42.59 106.91,42.59 106.874,42.605 106.837,42.616 98.878,49.198 98.875,49.203 98.87,49.206 98.855,49.241 98.837,49.275 98.839,49.281 98.836,49.286 98.836,60.1 98.87,60.18 98.95,60.214 166.608,60.214
VCC on Top Layer "Top Layer-VCC" (solid, remove dead copper, pour order 1001): 122.13,116.88 122.164,116.8 122.164,61 122.13,60.92 122.05,60.886 -1.45,60.886 -1.53,60.92 -1.564,61 -1.564,116.8 -1.53,116.88 -1.45,116.914 122.05,116.914
VCCINT on Top Layer "Top Layer-VCCINT" (solid, remove dead copper, pour order 1000): 166.55,53.214 166.551,53.214 166.59,53.197 166.63,53.18 166.631,53.18 166.647,53.14 166.664,53.1 166.664,53.099 166.364,-1.101 166.347,-1.14 166.33,-1.18 166.33,-1.181 166.29,-1.197 166.25,-1.214 91.95,-1.214 91.87,-1.18 91.836,-1.1 91.836,53.1 91.87,53.18 91.95,53.214 166.55,53.214
VCC on MidLayer1 "MidLayer1-VCC" (solid, remove dead copper, pour order 1005): 128.13,116.38 128.164,116.3 128.164,-3 128.13,-3.08 128.05,-3.114 -4.15,-3.114 -4.151,-3.113 -4.152,-3.114 -4.191,-3.097 -4.23,-3.08 -4.231,-3.079 -4.232,-3.079 -4.247,-3.039 -4.264,-3 -4.263,-2.999 -4.264,-2.998 -1.664,116.302 -1.647,116.341 -1.63,116.38 -1.629,116.381 -1.629,116.382 -1.589,116.397 -1.55,116.414 128.05,116.414
VCCINT on MidLayer1 "MidLayer1-VCCINT" (solid, remove dead copper, pour order 1004): 166.33,116.68 166.364,116.6 166.364,-1.2 166.33,-1.28 166.25,-1.314 73.464,-1.314 73.464,-2.4 73.447,-2.44 73.431,-2.48 73.43,-2.48 73.39,-2.497 73.35,-2.514 73.31,-2.497 73.27,-2.481 73.27,-2.48 73.253,-2.44 73.236,-2.4 73.036,44 73.053,44.04 73.069,44.08 73.07,44.08 73.109,44.097 73.15,44.114 111.903,44.114 124.636,56.847 124.636,116.6 124.67,116.68 124.75,116.714 166.25,116.714
GND on MidLayer2 "MidLayer2-GND 1" (solid, remove dead copper, pour order 1010): 117.476,118.223 117.476,118.224 167.006,117.589 167.046,117.572 167.085,117.555 167.086,117.555 167.086,117.554 167.102,117.515 167.119,117.475 167.119,52.07 167.085,51.99 167.005,51.956 117.475,51.956 117.395,51.99 117.361,52.07 117.361,118.11 117.362,118.111 117.361,118.111 117.378,118.151 117.395,118.19 117.395,118.191 117.396,118.191 117.435,118.207 117.475,118.224
GND on MidLayer2 "MidLayer2-GND" (solid, remove dead copper, pour order 1009): 16.59,61.675 19.097,59.169 25.353,59.169 27.225,61.04 27.305,61.074 34.925,61.074 35.005,61.04 45.165,50.88 45.199,50.8 45.199,19.732 47.705,17.225 47.715,17.202 47.739,17.145 47.739,-1.27 47.705,-1.35 47.625,-1.384 -1.905,-1.384 -1.906,-1.383 -1.906,-1.384 -1.946,-1.367 -1.985,-1.35 -1.986,-1.35 -2.002,-1.31 -2.019,-1.27 -2.018,-1.269 -2.019,-1.269 -1.384,61.596 -1.367,61.636 -1.35,61.675 -1.35,61.676 -1.31,61.692 -1.27,61.709 16.51,61.709
VCC on MidLayer2 "MidLayer2-VCC" (solid, remove dead copper, pour order 1008): 118.785,117.572 118.825,117.556 118.825,117.555 118.842,117.515 118.859,117.476 118.859,117.475 118.859,67.31 118.825,67.23 114.38,62.785 114.3,62.751 25.4,62.751 25.32,62.785 20.908,67.196 -2.54,67.196 -2.62,67.23 -2.654,67.31 -2.654,116.84 -2.637,116.88 -2.621,116.92 -2.62,116.92 -2.58,116.937 -2.541,116.954 118.744,117.589 118.745,117.589
VCCINT on MidLayer2 "MidLayer2-VCCINT" (solid, remove dead copper, pour order 1007): 168.276,42.658 168.276,42.659 168.316,42.642 168.355,42.625 168.356,42.625 168.356,42.624 168.372,42.585 168.389,42.545 168.388,42.544 168.389,42.544 167.754,-7.621 167.737,-7.661 167.72,-7.7 167.72,-7.701 167.719,-7.701 167.68,-7.717 167.64,-7.734 167.639,-7.733 167.639,-7.734 167.599,-7.717 167.56,-7.7 167.559,-7.7 167.559,-7.699 167.543,-7.66 167.526,-7.62 167.526,-3.289 71.12,-3.289 71.04,-3.255 71.006,-3.175 71.006,42.545 71.04,42.625 71.12,42.659 168.275,42.659
VCCAUX on MidLayer2 "MidLayer2-VCCAUX" (solid, remove dead copper, pour order 1006): 164.289,56.998 164.328,56.982 164.329,56.981 164.33,56.98 164.346,56.941 164.364,56.903 164.764,41.903 164.763,41.902 164.764,41.9 164.748,41.861 164.732,41.822 164.731,41.821 164.73,41.82 164.691,41.804 164.653,41.786 164.652,41.787 164.65,41.786 111.597,41.786 97.364,27.553 97.364,18.6 97.33,18.52 90.63,11.82 90.55,11.786 66.15,11.786 66.07,11.82 66.036,11.9 66.036,49.9 66.07,49.98 66.15,50.014 75.403,50.014 78.77,53.38 78.85,53.414 118.203,53.414 121.77,56.98 121.85,57.014 164.25,57.014
VCCINT on Bottom Layer "Bottom Layer-VCCINT" (solid, remove dead copper, pour order 1013): 168.13,66.18 168.164,66.1 168.164,-4.2 168.13,-4.28 168.05,-4.314 66.25,-4.314 66.17,-4.28 66.136,-4.2 66.136,45.6 66.17,45.68 66.25,45.714 107.503,45.714 119.27,57.48 119.35,57.514 141.803,57.514 150.47,66.18 150.55,66.214 168.05,66.214
VCC on Bottom Layer "Bottom Layer-VCC" (solid, remove dead copper, pour order 1012): 83.9,116.92 83.934,116.84 83.934,-7.62 83.9,-7.7 83.82,-7.734 -1.905,-7.734 -1.906,-7.734 -1.945,-7.717 -1.985,-7.7 -1.986,-7.7 -2.002,-7.66 -2.019,-7.62 -2.019,-7.619 -1.384,116.841 -1.367,116.88 -1.35,116.92 -1.35,116.921 -1.31,116.937 -1.27,116.954 83.82,116.954
GND on Bottom Layer "Bottom Layer-GND" (solid, remove dead copper, pour order 1011): 167.72,118.825 167.754,118.745 167.754,-3.81 167.72,-3.89 167.64,-3.924 -3.175,-3.924 -3.215,-3.907 -3.255,-3.891 -3.255,-3.89 -3.272,-3.85 -3.289,-3.811 -3.924,118.744 -3.924,118.745 -3.907,118.785 -3.891,118.825 -3.89,118.825 -3.851,118.842 -3.811,118.859 -3.81,118.859 167.64,118.859
VCC on VCC Plane (split plane): 164.298,0.802 0.802,0.802 0.802,114.209 164.298,114.209
GND on GND Plane (split plane): 164.298,0.802 48.15,0.802 48.15,22.7 48.147,22.729 48.144,22.759 48.127,22.815 48.117,22.833 48.099,22.867 48.079,22.892 48.062,22.912 47.15,23.824 47.15,35.7 47.147,35.729 47.144,35.759 47.127,35.815 47.117,35.833 47.099,35.867 47.079,35.892 47.062,35.912 45.65,37.324 45.65,41.976 47.062,43.388 47.079,43.408 47.099,43.433 47.117,43.467 47.127,43.485 47.144,43.541 47.147,43.571 47.15,43.6 47.15,53.176 49.362,55.388 49.379,55.408 49.399,55.433 49.417,55.467 49.427,55.485 49.444,55.541 49.447,55.571 49.45,55.6 49.45,60.8 49.444,60.859 49.427,60.915 49.399,60.967 49.362,61.012 49.317,61.049 49.265,61.077 49.209,61.094 49.15,61.1 49.091,61.094 49.035,61.077 48.983,61.049 48.938,61.012 48.901,60.967 48.873,60.915 48.856,60.859 48.85,60.8 48.85,55.724 46.638,53.512 46.601,53.467 46.573,53.415 46.556,53.359 46.553,53.329 46.55,53.3 46.55,43.724 45.138,42.312 45.101,42.267 45.073,42.215 45.056,42.159 45.053,42.129 45.05,42.1 45.05,37.2 45.053,37.171 45.056,37.141 45.073,37.085 45.101,37.033 45.138,36.988 46.55,35.576 46.55,23.7 46.553,23.671 46.556,23.641 46.573,23.585 46.601,23.533 46.638,23.488 47.55,22.576 47.55,0.802 0.802,0.802 0.802,114.209 164.298,114.209

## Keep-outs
Top Layer:
  circle w0.254: c134.62,73.66 r12.141
  circle w0.254: c30.48,73.66 r12.141
  lines w0.4: 117.15,24.6 117.15,23.4 129.15,23.4 129.15,24.6 ; 117.15,27.6 117.15,28.8 129.15,28.8 129.15,27.6
Keep-Out Layer:
  the board outline again, w0.8

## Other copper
Top Layer:
  region net VCC: 4.68,83.2 4.68,72.1 15.75,72.1 15.75,83.2
  rectangle net VCCAUX: 132.9,42.4 144.55,55.2
  rectangle net VCCINT: 133.55,20.2 143.95,31.8
VCC Plane (plane layer: these items are gaps in the copper):
  lines w1.8: 10.45,7.6 11.35,7.6 ; 10.45,13.2 11.35,13.2 ; 12.45,5.15 13.35,5.15 ; 12.45,11.3 13.35,11.3 ; 12.45,16.95 13.35,16.95 ; 21.95,7.6 22.85,7.6 ; 21.95,13.2 22.85,13.2 ; 23.95,5.15 24.85,5.15 ; 23.95,11.3 24.85,11.3 ; 23.95,16.95 24.85,16.95 ; 98.505,103.435 98.505,105.435 ; 102.255,101.235 104.755,101.235 ; 102.505,107.435 104.505,107.435
GND Plane (plane layer: these items are gaps in the copper):
  lines w0.254: 11.799,4.302 cw(c12.696,5.138) 11.818,5.994 ; 12.319,4.191 13.462,4.191 ; 12.338,6.109 13.481,6.109 ; 13.982,4.306 ccw(c13.104,5.162) 14.001,5.998 ; 23.299,4.302 cw(c24.196,5.138) 23.318,5.994 ; 23.819,4.191 24.962,4.191 ; 23.838,6.109 24.981,6.109 ; 25.482,4.306 ccw(c24.604,5.162) 25.501,5.998 ; 97.536,103.251 97.536,105.537 ; 97.622,102.762 ccw(c98.478,103.641) 99.314,102.743 ; 97.622,106.064 cw(c98.458,105.167) 99.314,106.045 ; 99.441,103.251 99.441,105.537 ; 101.876,106.552 cw(c102.773,107.388) 101.895,108.244 ; 102.403,106.466 104.689,106.466 ; 102.403,108.371 104.689,108.371 ; 105.178,106.552 ccw(c104.299,107.408) 105.197,108.244
  lines w0.597: 47.85,-0.1 47.85,22.7 46.85,23.7 46.85,35.7 45.35,37.2 45.35,42.1 46.85,43.6 46.85,53.3 49.15,55.6 49.15,60.8
  lines w1.8: 10.45,7.6 11.35,7.6 ; 10.45,13.2 11.35,13.2 ; 12.45,11.3 13.35,11.3 ; 12.45,16.95 13.35,16.95 ; 21.95,7.6 22.85,7.6 ; 21.95,13.2 22.85,13.2 ; 23.95,11.3 24.85,11.3 ; 23.95,16.95 24.85,16.95 ; 102.255,101.235 104.755,101.235

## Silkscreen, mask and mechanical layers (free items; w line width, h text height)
Top Overlay:
  circle w1: c96.95,111.254 r0.458
  circle w0.508: c134.62,73.66 r10
  circle w0.508: c30.48,73.66 r10
  circle w0.254: c159.918,5.08 r4
  circle w0.254: c5.08,5.08 r4
  circle w0.254: c5.08,109.931 r4
  circle w0.254: c159.969,109.931 r4
  rectangle: 44.55,63 57.05,73.5
  rectangle: 57.25,63 69.75,73.5
  rectangle: 69.95,63 82.45,73.5
  rectangle: 82.65,63 95.15,73.5
  rectangle: 95.35,63 107.85,73.5
  rectangle: 108.05,63 120.55,73.5
  lines w0.08: 2.178,34.055 2.178,38.119 ; 3.829,65.551 3.829,64.916 4.718,64.027 6.496,64.027 7.004,63.519 ; 6.75,34.055 6.75,38.119 ; 7.004,58.947 8.401,58.947 9.163,59.709 ; 9.036,34.309 9.036,38.119 ; 11.068,64.662 12.338,64.662 12.592,64.408 ; 11.703,25.8 11.703,24.276 11.957,24.022 ; 16.402,101.492 17.672,101.492 ; 16.656,34.309 16.656,38.119 ; 19.196,34.309 19.196,38.119 ; 21.863,34.309 21.863,38.119 ; 24.403,34.309 24.403,38.119 ; 26.943,34.309 26.943,38.119 ; 40.15,14.1 48.35,14.1 ; 47.39,97.555 47.644,97.555 48.279,96.92 ; 62.376,93.364 62.681,93.059 80.867,93.059 81.299,93.491 82.061,93.491 ; 85.617,94.253 80.791,94.253 ; 131.083,11.576 131.972,10.687 132.48,10.687 ; 152.038,76.981 152.038,77.362 ; 155.086,75.838 155.086,77.362 ; 157.118,63.9 158.388,65.17 ; 157.626,77.362 158.896,76.092 159.658,76.092 ; 48.35,14.1 47.65,14.2 47.65,14 48.35,14.1 ; 80.791,94.253 81.491,94.153 81.491,94.353 80.791,94.253
  lines w0.2: 1.605,30.075 1.605,34.795 ; 27.605,30.075 27.605,34.795 ; 93.013,111.254 94.029,111.254 ; 93.521,110.746 93.521,111.762 ; 94.537,111.254 96.061,111.254 ; 95.47,110.4 ccw(c96.95,111.254) 95.47,112.108
  text "GND" at 47.15,113.2 h1.1
  text "5 VDC" at 85.05,110.6 h1.5
  text "PWR" at 93.85,99.5 h1.1
  text "CTS" at 26.35,94.4 h1
  text "RTS" at 29.75,94.4 h1
  text "RXD" at 36.15,94.4 h1
  text "TXD" at 39.55,94.4 h1
  text "GND" at 161.15,38.1 h1.1
  text "GND" at 106.15,18.8 h1.1
  text "GND" at 31.35,12 h1.1
  text "LOADED" at 146.05,11.5 h1.1
  text "USER HEADER A" at 91.95,9.8 h1.1
  text "USER HEADER B" at 116.25,9.7 h1.1
  text "TEST/RESET" at 143.75,3.1 h1.1
  text "LINE" at 10.25,2.3 h1.1
  text "HEAD" at 20.95,2.3 h1.1
  text "VOLUME" at 30.35,1 h1.1
  text "5V" at 73.05,1 h1.1
  text "3V3" at 75.75,1 h1.1
  text "5V" at 108.65,1 h1.1
  text "3V3" at 111.35,1 h1.1
  text "OUT" at 10.25,0.8 h1.1
  text "PHONE" at 20.95,0.8 h1.1
Bottom Overlay:
  lines w0.08: 71.393,34.69 72.79,34.69 73.552,35.452 81.807,35.452 82.188,35.833 82.188,36.341 ; 73.806,39.008 75.457,37.357 77.616,37.357 ; 76.092,41.675 76.092,43.961 ; 76.219,25.8 76.219,28.34 ; 80.918,26.689 80.918,28.34 ; 82.95,33.674 82.95,33.928 83.458,34.436 91.713,34.436 ; 84.982,41.675 84.982,43.072 ; 87.014,43.707 87.014,44.596 ; 88.538,28.34 89.3,27.578 89.3,27.07 ; 88.919,41.675 88.919,43.453
Unplated Route Details:
  lines w2.4: 0,-1.2 51.7,-1.2 ; 0,116.211 51.7,116.211 ; 56.7,-1.2 108.4,-1.2 ; 56.7,116.211 108.4,116.211 ; 113.4,-1.2 165.1,-1.2 ; 113.4,116.211 165.1,116.211
Unit PCB Boundaries:
  the board outline again, w0.2
  text "Unit PCB boundaries coincide with centre-lines of tracks" at 0,-8 h0.75
Gerber ID:
  text ".Layer_Name" at 0,-6 h0.75
Dimensions:
  text "Dimensions in millimetres" at 0,-10 h0.75
Design Information:
  drawing of 719 lines, arcs and shapes, not listed
  text "EB1 REV1.02" at 313.547,253.474 h1.27
  text "DESIGN INFORMATION" at 257.54,253.347 h1.52
  text "BOARD NAME:" at 295.132,253.347 h1.52
  text "BOARD TECHNOLOGY" at 257.54,250.807 h1.52
  text "BOARD SIZE (REFER ALSO PROFILING INFORMATION)" at 305.8,250.807 h1.27
  text "115.01mm" at 313.52,248.533 h1.52
  text "11.811" at 273.339,248.445 h1.52
  text "165.10mm" at 336.52,248.433 h1.52
  text "7.874" at 287.309,248.318 h1.52
  text "5.000" at 260.366,248.267 h1.52
  text "(Unit)" at 352.59,248.209 h1.52
  text "X" at 329.469,247.759 h1.78
  text "(MIN. TRACK/   PADS  /CLEARANCE IN 0.001'')" at 256.016,245.727 h1.27
  text "MINIMUM ANNULAR RING 0.05MM (0.002'') EXTERNAL PER IPC-2221 CLASS 3 LEVEL C AND IS THE" at 257.54,243.187 h1.27
  text "MANUFACTURING REGISTRATION ALLOWANCE" at 257.54,240.901 h1.27
  text "LAND SIZE CALCULATION MINIMUM - NOMINAL HOLE SIZE + 0.508MM (0.020'')" at 257.54,238.107 h1.27
  text "AS INSTRUCTED" at 343.57,233.713 h1.52
  text "X" at 295.183,233.586 h1.52
  text "CIRCUIT TYPE:" at 257.54,233.535 h1.52
  text "SS" at 280.4,233.535 h1.27
  text "DS" at 298.18,233.535 h1.27
  text "X" at 312.785,233.535 h1.52
  text "PTH" at 315.96,233.535 h1.27
  text "ML" at 326.882,233.535 h1.27
  text "X" at 330.692,233.535 h1.52
  text "No. OFF" at 333.74,233.535 h1.27
  text "FINGER CONNECTOR DIM PER:" at 257.54,230.487 h1.52
  text "AS SHOWN" at 333.74,230.487 h1.27
  text "No. OFF TOTAL" at 274.304,227.693 h1.52
  text "ONE SIDE" at 315.96,227.693 h1.27
  text "BOTH SIDES" at 333.74,227.439 h1.27
  text "VIAS:" at 257.54,224.772 h1.52
  text "NONE" at 268.97,224.772 h1.14
  text "X" at 277.352,224.772 h1.52
  text "FEED THRU'" at 280.4,224.772 h1.14
  text "X" at 295.132,224.772 h1.52
  text "TENTED" at 298.18,224.772 h1.14
  text "BURIED LAYER SEQUENCE" at 315.96,224.772 h1.14
  text "UNIQUE DRILL" at 280.4,221.724 h1.14
  text "2 SIZE" at 298.18,221.724 h1.14
  text "BLIND LAYER SEQUENCE" at 315.96,221.724 h1.14
  text "Layer Stack Manager (Protel)" at 292.973,219.438 h1.27
  text "X" at 330.692,219.438 h1.52
  text "AS SHOWN" at 333.74,219.438 h1.27
  text "LAYER CONSTRUCTION PER:" at 257.54,219.311 h1.52
  text "Protel" at 338.566,216.771 h1.27
  text "(PFW)" at 348.853,216.644 h1.27
  text "ARTWORK:" at 257.54,216.517 h1.52
  text "MANUAL" at 280.4,216.517 h1.27
  text "DIGITISED" at 298.18,216.517 h1.27
  text "X" at 312.912,216.517 h1.52
  text "CAD" at 315.96,216.517 h1.27
  text "TYPE" at 326.882,216.517 h1.27
  text "ARTWORK/PATTERN MASTER LIST" at 257.54,211.818 h1.52
  text "DESCRIPTION" at 258.81,209.405 h1.27
  text "DRAWING No./CAD FILE REF." at 277.479,209.405 h1.27
  text "LAYER NAME" at 318.754,209.405 h1.27
  text "GERBER FILE REF" at 339.506,209.329 h1.27
  text "PCB FILE" at 257.256,206.941 h1.27
  text "EB_Spartan_III" at 277.627,206.865 h1.27
  text "PcbDoc" at 308.869,206.865 h1.02
  text "Top Paste Mask" at 317.048,204.401 h1.02
  text "GTP" at 359.669,204.325 h1.27
  text "GERBER FILE" at 257.256,204.274 h1.27
  text "GTO" at 359.618,201.836 h1.27
  text "Top Overlay" at 317.048,201.81 h1.02
  text "GERBER FILE" at 257.256,201.734 h1.27
  text "Top Solder Mask" at 317.048,199.372 h1.02
  text "GTS" at 359.669,199.245 h1.27
  text "GERBER FILE" at 257.256,199.194 h1.27
  text "TOP LAYER" at 317.048,196.781 h1.02
  text "GTL" at 359.669,196.705 h1.27
  text "GERBER FILE" at 257.256,196.654 h1.27
  text "GERBER FILE" at 257.256,194.114 h1.27
  text "MIDLAYER1" at 317.19,194.109 h1.02
  text "G1" at 359.69,194.109 h1.27
  text "INTERNALPLANE1" at 317.048,191.741 h1.02
  text "GERBER FILE" at 257.256,191.574 h1.27
  text "GP1" at 359.669,191.565 h1.27
  text "INTERNALPLANE2" at 317.048,189.201 h1.02
  text "GP2" at 359.618,189.076 h1.27
  text "GERBER FILE" at 257.256,189.034 h1.27
  text "MIDLAYER2" at 317.048,186.661 h1.02
  text "GERBER FILE" at 257.256,186.494 h1.27
  text "G2" at 359.69,186.509 h1.27
  text "BOTTOMLAYER" at 317.048,184.101 h1.02
  text "GBL" at 359.669,184.025 h1.27
  text "GERBER FILE" at 257.256,183.954 h1.27
  text "Bottom Solder Mask" at 317.048,181.612 h1.02
  text "GBS" at 359.669,181.485 h1.27
  text "GERBER FILE" at 257.256,181.414 h1.27
  text "Bottom Overlay" at 317.048,179.021 h1.02
  text "GBO" at 359.669,178.945 h1.27
  text "GERBER FILE" at 257.256,178.874 h1.27
  text "Bottom Paste Mask" at 317.048,176.532 h1.02
  text "GBP" at 359.669,176.405 h1.27
  text "GERBER FILE" at 257.256,176.334 h1.27
  text "PCB Boundary" at 317.048,173.941 h1.02
  text "GM5" at 359.669,173.865 h1.27
  text "GERBER FILE" at 257.256,173.794 h1.27
  text "Peelable Solder Mask" at 317.048,171.401 h1.02
  text "GM2" at 359.669,171.325 h1.27
  text "GERBER FILE" at 257.256,171.254 h1.27
  text "Unplated Route Details" at 317.048,168.861 h1.02
  text "GM3" at 359.669,168.785 h1.27
  text "GERBER FILE" at 257.256,168.714 h1.27
  text "Plated Route Details" at 317.048,166.321 h1.02
  text "GM4" at 359.669,166.245 h1.27
  text "GERBER FILE" at 257.256,166.174 h1.27
  text "APERTURE LIST" at 257.256,163.811 h1.27
  text "APR" at 309.869,163.735 h1.27
  text "DRILL REPORT" at 257.256,161.271 h1.27
  text "DRR" at 309.869,161.195 h1.27
  text "EXCELLON DRILL" at 257.256,158.731 h1.27
  text "TXT" at 309.869,158.655 h1.27
  text "MATERIAL:" at 257.54,150.731 h1.52
  text "GLASS FIBRE EPOXY RESIN NEMA GRADE FR4 (MIL-S-13949H)" at 283.194,150.477 h1.27
  text "X" at 280.527,150.35 h1.52
  text "THICKNESS:" at 265.414,147.556 h1.27
  text "0.8mm" at 283.194,147.556 h1.27
  text "1.2mm" at 300.847,147.556 h1.27
  text "1.6mm" at 318.5,147.556 h1.27
  text "2.4mm" at 336.28,147.556 h1.27
  text "3.2mm" at 354.06,147.556 h1.27
  text "X" at 316.087,147.429 h1.52
  text "TOLERANCE:" at 265.287,144.508 h1.27
  text "IN A/W IPC-D-300G CLASS" at 282.94,144.508 h1.27
  text "3 LEVEL B" at 317.865,144.508 h1.27
  text "OTHER +/-" at 336.28,144.508 h1.27
  text "X" at 280.527,144.381 h1.52
  text "BOW & TWIST:" at 262.874,141.46 h1.27
  text "IN A/W IPC-D-300G CLASS" at 282.94,141.46 h1.27
  text "3 LEVEL B" at 317.865,141.46 h1.27
  text "AS SHOWN" at 336.407,141.333 h1.27
  text "X" at 280.527,141.206 h1.52
  text "COPPER THICKNESS (FINISHED)" at 265.287,138.158 h1.27
  text "OUTER:" at 270.113,135.872 h1.27
  text "18um" at 283.194,135.872 h1.27
  text "35um" at 310.245,135.872 h1.27
  text "70um" at 336.534,135.872 h1.27
  text "X" at 307.502,135.669 h1.52
  text "INNER SIGNAL:" at 261.731,132.824 h1.27
  text "18um" at 283.194,132.824 h1.27
  text "35um" at 310.245,132.824 h1.27
  text "70um" at 336.534,132.824 h1.27
  text "X" at 307.451,132.621 h1.52
  text "INNER PWR:" at 265.414,129.776 h1.27
  text "18um" at 283.194,129.776 h1.27
  text "35um" at 310.245,129.776 h1.27
  text "70um" at 336.534,129.776 h1.27
  text "X" at 307.578,129.649 h1.52
  text "STRUCTURE:" at 257.54,126.728 h1.52
  text "REFER" at 283.194,126.728 h1.27
  text "AS PER DRAWING No." at 283.067,123.553 h1.27
  text "AS SHOWN" at 336.407,123.553 h1.27
  text "X" at 333.867,123.426 h1.52
  text "DRILLING:" at 257.54,120.759 h1.52
  text "VIEWED FROM:" at 262.493,118.473 h1.27
  text "COMPONENT SIDE" at 283.194,118.473 h1.14
  text "SOLDER SIDE" at 309.991,118.473 h1.14
  text "X" at 280.527,118.219 h1.52
  text "REFERENCE:" at 264.779,115.425 h1.27
  text "AS SHOWN" at 283.067,115.298 h1.14
  text "PATTERN MASTER LIST" at 310.118,115.298 h1.14
  text "X" at 333.867,115.298 h1.52
  text "NC_DRILL FILES" at 336.407,115.298 h1.14
  text "X" at 280.527,115.171 h1.52
  text "PTH MINIMUM COPPER THICKNESS:" at 270.621,112.377 h1.27
  text "20um" at 310.245,112.377 h1.27
  text "X" at 307.578,112.25 h1.52
  text "OTHER" at 336.407,112.25 h1.27
  text "NPTH:" at 271.129,109.329 h1.27
  text "TENTED" at 283.067,109.202 h1.14
  text "X" at 307.578,109.202 h1.52
  text "PADS REMOVED" at 310.118,109.202 h1.14
  text "REMOVE PADS" at 336.407,109.202 h1.14
  text "X" at 280.527,109.075 h1.52
  text "2nd DRILL" at 283.067,106.154 h1.14
  text "BOTH" at 310.118,106.154 h1.14
  text "AS SHOWN" at 322.437,106.154 h1.14
  text "NONE" at 336.407,106.154 h1.14
  text "BOARD FINISH:" at 257.54,103.233 h1.52
  text "X" at 280.527,103.106 h1.52
  text "ETCHING" at 283.067,103.106 h1.14
  text "REFER PATTERN MASTER LIST" at 310.118,103.106 h1.14
  text "LEGEND / SCREEN PRINT:" at 277.86,100.185 h1.27
  text "NONE" at 310.118,100.058 h1.14
  text "COMPONENT" at 322.437,100.058 h1.14
  text "SOLDER" at 336.407,100.058 h1.14
  text "X" at 319.897,99.931 h1.52
  text "X" at 333.867,99.931 h1.52
  text "COLOUR:" at 268.081,97.137 h1.27
  text "WHITE" at 283.067,97.01 h1.14
  text "YELLOW" at 310.118,97.01 h1.14
  text "OTHER" at 336.407,97.01 h1.14
  text "X" at 280.527,96.883 h1.52
  text "X" at 280.527,93.962 h1.52
  text "LIQUID PHOTOIMAGEABLE" at 283.067,93.962 h1.14
  text "SCREEN PRINT" at 322.437,93.962 h1.14
  text "MATTE" at 283.067,90.914 h1.14
  text "GLOSS" at 295.767,90.914 h1.14
  text "GREEN" at 310.118,90.914 h1.14
  text "BLUE" at 322.437,90.914 h1.14
  text "G/Y" at 336.407,90.914 h1.14
  text "OTHER" at 347.837,90.914 h1.14
  text "X" at 293.1,90.787 h1.52
  text "SOLDER MASK COLOUR:" at 257.54,87.993 h1.14
  text "BLACK" at 283.067,87.866 h1.14
  text "GREEN" at 295.767,87.866 h1.14
  text "YELLOW" at 310.118,87.866 h1.14
  text "BLUE" at 322.437,87.866 h1.14
  text "OTHER" at 336.407,87.866 h1.14
  text "X" at 280.4,87.739 h1.52
  text "TRACK FINISH:" at 257.54,84.945 h1.52
  text "SELECTIVE SOLDER (HASL)" at 283.067,84.818 h1.14
  text "REFLOW SOLDER" at 322.437,84.818 h1.14
  text "SELECTIVE GOLD" at 283.067,81.77 h1.14
  text "um  (AREA" at 310.118,81.77 h1.14
  text "sq. mm)" at 337.931,81.77 h1.14
  text "IMMERSION GOLD" at 330.69,79.409 h1.27
  text "REFER PATTERN MASTER LIST" at 283.067,78.722 h1.14
  text "OTHER" at 322.437,78.722 h1.14
  text "X" at 319.927,78.718 h1.52
  text "EDGE BOARD" at 257.54,75.801 h1.52
  text "1.3um HARD GOLD OVER 5um     NICKEL / TIN-NICKEL" at 283.067,75.674 h1.14
  text "CONTACTS:" at 257.54,73.642 h1.52
  text "HARD FINISH GOLDE PLATE" at 283.067,72.626 h1.14
  text "OTHER" at 322.437,72.626 h1.14
  text "AS SHOWN" at 283.067,69.578 h1.14
  text "REFER" at 322.437,69.578 h1.14
  text "PROFILING:" at 257.54,66.53 h1.52
  text "AS DIMENSIONED, MEASURED AND CUT FROM SPECIFIED DATUM." at 283.067,66.53 h1.14
  text "X" at 280.527,66.403 h1.52
  text "REFER PCB BLANK DWG No." at 283.194,63.609 h1.27
  text "USE PROFILE / ROUTE TAPE SUPPLIED (REFER PATTERN MASTER LIST)" at 283.194,60.561 h1.27
  text "SQUARE CUT" at 283.194,57.513 h1.27
  text "N.C. ROUTE" at 300.974,57.513 h1.27
  text "V. SCORE" at 318.754,57.513 h1.27
  text "BLANK" at 336.534,57.513 h1.27
  text "ACCEPTABILITY:" at 257.54,54.846 h1.52
  text "MATERIALS AND WORKMANSHIP FOR ALL PRINTED WIRING BOARDS TO MEET" at 279.765,54.719 h1.27
  text "OR EXCEED THE REQUIREMENTS OF:" at 279.765,51.925 h1.27
  text "IPC-6011/12 AND IPC-A-600E" at 283.321,49.258 h1.27
  text "1" at 318.881,49.258 h1.27
  text "2" at 327.771,49.258 h1.27
  text "X" at 325.104,49.131 h1.52
  text "X" at 280.654,49.004 h1.52
  text "3" at 336.661,47.099 h1.27
  text "UL CERTIFICATION" at 283.321,46.21 h1.27
  text "AUSTEL" at 318.881,46.21 h1.27
  text "X" at 280.654,46.083 h1.52
  text "ML-P-55110F GRP" at 282.813,43.162 h1.02
  text "A" at 301.101,43.162 h1.27
  text "B" at 309.991,43.162 h1.27
  text "AS2546" at 318.881,43.162 h1.27
  text "OTHER" at 336.661,43.162 h1.27
  text "ADDITIONAL" at 257.54,40.241 h1.52
  text "NONE" at 283.321,39.987 h1.27
  text "SAMPLE PLAN" at 301.101,39.987 h1.27
  text "MIL-P-55110E SERIAL Nos. PER ORDER" at 318.881,39.987 h1.27
  text "REQUIREMENTS:" at 257.54,37.828 h1.52
  text "NONE" at 283.321,36.939 h1.27
  text "ML-P-55110F GRP" at 300.593,36.939 h1.02
  text "A" at 318.881,36.939 h1.27
  text "B" at 327.771,36.939 h1.27
  text "IPC CLASS:" at 333.74,36.939 h1.27
  text "1" at 349.234,36.939 h1.27
  text "2" at 355.584,36.939 h1.27
  text "3" at 361.934,36.939 h1.27
  text "QUALITY RELEASE REPORT" at 301.101,33.891 h1.27
  text "OTHER" at 341.614,33.891 h1.27
  text "PER ORDER" at 350.123,33.764 h1.27
  text "X" at 338.947,33.637 h1.52
  text "NONE" at 301.101,30.843 h1.27
  text "REQUIRED" at 318.881,30.843 h1.27
  text "PER ORDER" at 341.741,30.843 h1.27
  text "ELECTRICAL TEST:" at 257.54,30.716 h1.52
  text "X" at 316.214,30.716 h1.52
  text "NONE" at 301.101,27.795 h1.27
  text "1 SIDE" at 318.754,27.795 h1.14
  text "2 SIDES" at 329.93,27.795 h1.14
  text "MIN. PITCH" at 341.614,27.795 h1.27
  text "0.65mm" at 355.203,27.795 h1.27
  text "SURFACE MOUNT:" at 257.54,27.668 h1.52
  text "X" at 327.695,27.592 h1.52
  text "NONE" at 301.101,24.747 h1.27
  text "FOIL" at 318.881,24.747 h1.27
  text "LEGEND" at 330.311,24.747 h1.27
  text "REFER" at 341.614,24.747 h1.27
  text "MANUFACTURER'S ID/LOGO:" at 257.54,24.62 h1.52
  text "ISO9001/AS3901" at 304.911,21.699 h1.27
  text "NONE" at 341.614,21.699 h1.27
  text "MANUFACTURER'S ACCREDITATION:" at 257.54,21.572 h1.52
  text "X" at 302.244,21.572 h1.52
  text "PER ORDER" at 301.101,18.651 h1.27
  text "REFER" at 318.881,18.651 h1.27
  text "PACKAGING AND HANDLING:" at 257.54,18.524 h1.52
  text "X" at 298.434,18.397 h1.52
Mechanical 15:
  lines w0.2: 82.55,0 82.55,114.935
Sheet:
  drawing of 1882 lines, arcs and shapes, not listed
  text "1" at 4.117,258.591 h1.78
  text "2" at 53.156,258.591 h1.78
  text "3" at 102.415,258.591 h1.78
  text "4" at 151.708,258.591 h1.78
  text "5" at 200.984,258.591 h1.78
  text "6" at 250.006,258.591 h1.78
  text "7" at 299.536,258.591 h1.78
  text "8" at 348.558,258.591 h1.78
  text "A" at -18.015,224.606 h1.78
  text "A" at 370.605,224.606 h1.78
  text "B" at -18.015,153.994 h1.78
  text "B" at 370.605,153.994 h1.78
  text "C" at -18.015,83.382 h1.78
  text "C" at 370.605,83.382 h1.78
  text "D" at -18.015,13.278 h1.78
  text "D" at 370.605,13.278 h1.78
  text "ENGINEER:" at 255.67,13.1 h1.14
  text "TITLE:" at 293.77,13.1 h1.14
  text "PCB DESIGNER:" at 255.67,5.607 h1.14
  text "DATE:" at 255.67,-2.14 h1.14
  text "PART NO.:" at 293.77,-2.14 h1.14
  text "REV:" at 347.11,-2.14 h1.14
  text "Altium Limited" at 222.65,-4.68 h1.78
  text ".PRINT_DATE" at 256.94,-5.188 h1.78
  text "12a Rodborough Rd" at 222.65,-7.22 h1.78
  text "Frenchs Forest" at 222.65,-9.76 h1.78
  text "FILE NAME:" at 255.67,-9.76 h1.14
  text "DWG NO:" at 293.77,-9.76 h1.14
  text "SCALE:" at 347.11,-9.76 h1.14
  text "NSW 2086" at 222.65,-12.3 h1.78
  text ".PCB_FILE_NAME_NO_PATH" at 256.94,-12.808 h1.78
  text "1" at 4.117,-18.269 h1.78
  text "2" at 53.156,-18.269 h1.78
  text "3" at 102.415,-18.269 h1.78
  text "4" at 151.708,-18.269 h1.78
  text "5" at 200.984,-18.269 h1.78
  text "6" at 250.006,-18.269 h1.78
  text "7" at 299.536,-18.269 h1.78
  text "8" at 348.558,-18.269 h1.78
Drill Drawing:
  text ".Legend" at 168,0 h0.75

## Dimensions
0,0 to 0,115.011 on Dimensions
0,0 to 165.1,0 on Dimensions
